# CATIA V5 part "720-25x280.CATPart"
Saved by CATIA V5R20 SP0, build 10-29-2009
Part number: 720-25x280
Definition: NONE
Nomenclature: 720-25x280
Source: Unknown
Description: 720-25x280
Bounding box of the stored display mesh (mm): x 0 to 280, y -12.5 to 12.5, z -12.5 to 12.5
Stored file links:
  C:\Users\Utente\Desktop\IO LAVORO\3D X SITO CF\X SITO\720\720-25x280.CATPart
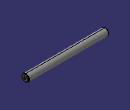
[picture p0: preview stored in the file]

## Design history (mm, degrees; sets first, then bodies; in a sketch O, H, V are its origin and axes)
Body1 "720-25x280" (main body)
  Solid1: solid without history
